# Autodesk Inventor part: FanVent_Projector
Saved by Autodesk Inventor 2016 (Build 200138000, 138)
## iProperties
Created: 2016-01
Part Number: FanVent_Projector
Material: Generic
Document SubType Name: Modeling
Designer: John
Density: 1 g/cm^3
Appearance: Default
Author: John
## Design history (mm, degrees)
feature "Base1"
body "Solid1"
